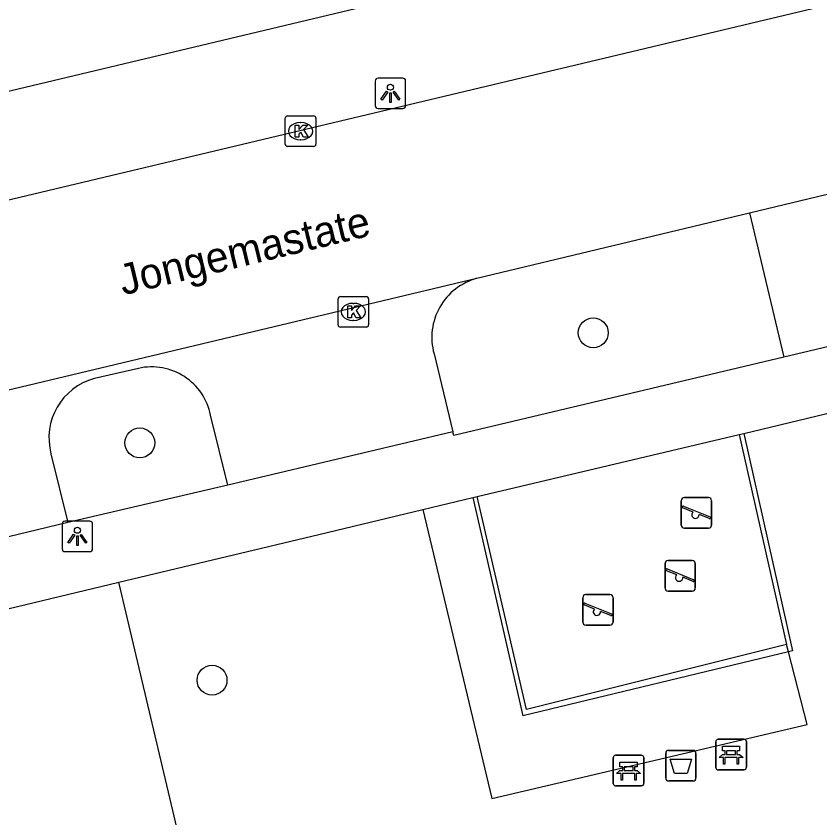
# Model space of a CAD drawing. Extents: x 158038 to 159242, y 380133 to 381214.
# Drawn here: x 158748.37 to 158774.69, y 380454.52 to 380480.77 of the extents above; entities that cross this region are included whole.
import ezdxf

# ---------------------------------------------------------------- set-up
doc = ezdxf.new("R2010")
doc.units = 0
for name, color, linetype in [('IMGEO_Afvalbak', 7, 'Continuous'), ('IMGEO_Bank', 7, 'Continuous'), ('IMGEO_Boom', 7, 'Continuous'), ('IMGEO_Groenvoorziening', 7, 'Continuous'), ('IMGEO_Hek', 7, 'Continuous'), ('IMGEO_Kolk', 7, 'Continuous'), ('IMGEO_Lichtpunt', 7, 'Continuous'), ('IMGEO_Openbare_ruimte_label', 7, 'Continuous'), ('IMGEO_Parkeervlak_open', 7, 'Continuous'), ('IMGEO_Rijbaan_lokaal_open', 7, 'Continuous'), ('IMGEO_Speelvoorziening', 7, 'Continuous'), ('IMGEO_Voetpad_open', 7, 'Continuous')]:
    doc.layers.add(name, color=color, linetype=linetype)

msp = doc.modelspace()

# ---------------------------------------------------------------- linework, layer by layer
at = {"layer": 'IMGEO_Afvalbak'}
for p, q in [((158769.638, 380455.829), (158769.638, 380456.629)), ((158769.638, 380456.629), (158769.638, 380455.829)), ((158769.738, 380456.729), (158770.528, 380456.729)), ((158770.528, 380456.729), (158769.738, 380456.729)), ((158770.628, 380456.629), (158770.628, 380455.829)), ((158770.628, 380455.829), (158770.628, 380456.629)), ((158770.528, 380455.729), (158769.738, 380455.729)), ((158769.738, 380455.729), (158770.528, 380455.729))]:
    msp.add_line(p, q, dxfattribs=at)
msp.add_lwpolyline([(158769.781, 380456.443), (158770.485, 380456.443), (158770.336, 380455.973), (158769.93, 380455.973), (158769.781, 380456.443)], dxfattribs=at)
for centre, start, end in [((158769.738, 380456.629), 90, 180), ((158769.738, 380456.629), 90, 180), ((158770.528, 380456.629), 0, 90), ((158770.528, 380456.629), 360, 90), ((158769.738, 380455.829), 180, 270), ((158769.738, 380455.829), 180, 270), ((158770.528, 380455.829), 270, 0), ((158770.528, 380455.829), 270, 0)]:
    msp.add_arc(centre, 0.1, start, end, dxfattribs=at)
at = {"layer": 'IMGEO_Bank'}
for p, q in [((158771.353, 380457.094), (158772.194, 380457.094)), ((158772.194, 380457.094), (158771.353, 380457.094)), ((158771.278, 380456.169), (158771.278, 380457.01)), ((158771.278, 380457.01), (158771.278, 380456.169)), ((158772.278, 380457.019), (158772.278, 380456.178)), ((158772.278, 380456.178), (158772.278, 380457.019)), ((158767.996, 380456.57), (158768.837, 380456.57)), ((158768.837, 380456.57), (158767.996, 380456.57)), ((158771.587, 380456.6), (158771.587, 380456.706)), ((158771.631, 380456.706), (158771.631, 380456.6)), ((158771.919, 380456.712), (158771.637, 380456.712)), ((158771.637, 380456.594), (158771.919, 380456.594)), ((158771.925, 380456.6), (158771.925, 380456.706)), ((158771.969, 380456.706), (158771.969, 380456.6)), ((158767.921, 380455.645), (158767.921, 380456.486)), ((158767.921, 380456.486), (158767.921, 380455.645)), ((158768.921, 380456.495), (158768.921, 380455.654)), ((158768.921, 380455.654), (158768.921, 380456.495)), ((158771.975, 380456.492), (158771.582, 380456.492)), ((158768.23, 380456.076), (158768.23, 380456.182)), ((158768.274, 380456.182), (158768.274, 380456.076)), ((158768.562, 380456.188), (158768.28, 380456.188)), ((158768.28, 380456.07), (158768.562, 380456.07)), ((158768.568, 380456.076), (158768.568, 380456.182)), ((158768.612, 380456.182), (158768.612, 380456.076)), ((158772.203, 380456.094), (158771.362, 380456.094)), ((158771.362, 380456.094), (158772.203, 380456.094)), ((158768.618, 380455.968), (158768.225, 380455.968)), ((158768.846, 380455.57), (158768.005, 380455.57)), ((158768.005, 380455.57), (158768.846, 380455.57))]:
    msp.add_line(p, q, dxfattribs=at)
for points in [[(158771.581, 380456.712), (158771.495, 380456.712), (158771.495, 380456.873), (158772.058, 380456.873), (158772.058, 380456.712), (158771.975, 380456.712)], [(158771.525, 380456.492), (158771.383, 380456.492), (158771.495, 380456.594), (158771.581, 380456.594)], [(158771.975, 380456.594), (158772.058, 380456.594), (158772.17, 380456.492), (158772.031, 380456.492)], [(158768.224, 380456.188), (158768.138, 380456.188), (158768.138, 380456.349), (158768.701, 380456.349), (158768.701, 380456.188), (158768.618, 380456.188)], [(158771.575, 380456.485), (158771.575, 380456.278), (158771.532, 380456.278), (158771.532, 380456.485)], [(158772.025, 380456.485), (158772.025, 380456.278), (158771.981, 380456.278), (158771.981, 380456.485)], [(158768.168, 380455.968), (158768.026, 380455.968), (158768.138, 380456.07), (158768.224, 380456.07)], [(158768.618, 380456.07), (158768.701, 380456.07), (158768.813, 380455.968), (158768.674, 380455.968)], [(158768.218, 380455.961), (158768.218, 380455.754), (158768.175, 380455.754), (158768.175, 380455.961)], [(158768.668, 380455.961), (158768.668, 380455.754), (158768.624, 380455.754), (158768.624, 380455.961)]]:
    msp.add_lwpolyline(points, dxfattribs=at)
for centre, radius, start, end in [((158771.356, 380457.016), 0.0779, 92.4484, 184.2845), ((158771.356, 380457.016), 0.0779, 92.4484, 184.2845), ((158772.2, 380457.016), 0.0779, 2.4484, 94.2845), ((158772.2, 380457.016), 0.0779, 2.4484, 94.2845), ((158767.999, 380456.492), 0.0779, 92.4484, 184.2845), ((158767.999, 380456.492), 0.0779, 92.4484, 184.2845), ((158768.843, 380456.492), 0.0779, 2.4484, 94.2845), ((158768.843, 380456.492), 0.0779, 2.4484, 94.2845), ((158771.58, 380456.705), 0.00671, 2.8957, 87.1043), ((158771.58, 380456.601), 0.00671, 272.8957, 357.1043), ((158771.637, 380456.705), 0.00671, 92.8957, 177.1043), ((158771.637, 380456.601), 0.00671, 182.8957, 267.1043), ((158771.919, 380456.705), 0.00671, 2.8957, 87.1043), ((158771.919, 380456.601), 0.00671, 272.8957, 357.1043), ((158771.976, 380456.705), 0.00671, 92.8957, 177.1043), ((158771.976, 380456.601), 0.00671, 182.8957, 267.1043), ((158771.525, 380456.485), 0.00671, 2.8957, 87.1043), ((158771.582, 380456.485), 0.00671, 92.8957, 177.1043), ((158771.974, 380456.485), 0.00671, 2.8957, 87.1043), ((158772.031, 380456.485), 0.00671, 92.8957, 177.1043), ((158768.223, 380456.181), 0.00671, 2.8957, 87.1043), ((158768.223, 380456.077), 0.00671, 272.8957, 357.1043), ((158768.28, 380456.181), 0.00671, 92.8957, 177.1043), ((158768.28, 380456.077), 0.00671, 182.8957, 267.1043), ((158768.562, 380456.181), 0.00671, 2.8957, 87.1043), ((158768.562, 380456.077), 0.00671, 272.8957, 357.1043), ((158768.619, 380456.181), 0.00671, 92.8957, 177.1043), ((158768.619, 380456.077), 0.00671, 182.8957, 267.1043), ((158771.356, 380456.172), 0.0779, 182.4484, 274.2845), ((158771.356, 380456.172), 0.0779, 182.4484, 274.2845), ((158772.2, 380456.172), 0.0779, 272.4484, 4.2845), ((158772.2, 380456.172), 0.0779, 272.4484, 4.2845), ((158768.168, 380455.961), 0.00671, 2.8957, 87.1043), ((158768.225, 380455.961), 0.00671, 92.8957, 177.1043), ((158768.617, 380455.961), 0.00671, 2.8957, 87.1043), ((158768.674, 380455.961), 0.00671, 92.8957, 177.1043), ((158767.999, 380455.648), 0.0779, 182.4484, 274.2845), ((158767.999, 380455.648), 0.0779, 182.4484, 274.2845), ((158768.843, 380455.648), 0.0779, 272.4484, 4.2845), ((158768.843, 380455.648), 0.0779, 272.4484, 4.2845)]:
    msp.add_arc(centre, radius, start, end, dxfattribs=at)
at = {"layer": 'IMGEO_Boom'}
for centre in [(158767.265, 380470.403), (158752.42, 380466.797), (158754.786, 380459.028)]:
    msp.add_circle(centre, 0.489, dxfattribs=at)
at = {"layer": 'IMGEO_Groenvoorziening'}
for points in [[(158772.376, 380474.328), (158773.5, 380469.6)], [(158772.046, 380467.073), (158773.593, 380460.202)], [(158674.708, 380422.973), (158675.136, 380421.076), (158676.506, 380415.389), (158677.716, 380410.364), (158686.692, 380412.003), (158702.709, 380415.812), (158716.247, 380419.298), (158716.347, 380418.923), (158726.817, 380421.283), (158741.196, 380424.551), (158759.516, 380429.33), (158758.315, 380434.41), (158751.736, 380462.236)]]:
    msp.add_lwpolyline(points, dxfattribs=at)
at = {"layer": 'IMGEO_Hek'}
for points in [[(158772.046, 380467.073), (158772.195, 380467.109)], [(158772.195, 380467.109), (158773.788, 380459.994)], [(158763.465, 380465.045), (158772.046, 380467.073)], [(158763.327, 380465.012), (158763.465, 380465.045)], [(158763.327, 380465.012), (158764.965, 380457.863)], [(158773.788, 380459.994), (158773.655, 380459.962)], [(158773.655, 380459.962), (158764.965, 380457.863)]]:
    msp.add_lwpolyline(points, dxfattribs=at)
at = {"layer": 'IMGEO_Kolk'}
for p, q in [((158757.184, 380476.579), (158757.184, 380477.431)), ((158757.259, 380477.505), (158758.111, 380477.505)), ((158758.185, 380477.431), (158758.185, 380476.579)), ((158757.672, 380477.285), (158757.697, 380477.285)), ((158757.695, 380476.725), (158757.67, 380476.725)), ((158758.111, 380476.505), (158757.259, 380476.505)), ((158758.986, 380471.587), (158759.838, 380471.587)), ((158758.911, 380470.661), (158758.911, 380471.513)), ((158759.399, 380471.367), (158759.424, 380471.367)), ((158759.912, 380471.513), (158759.912, 380470.661)), ((158759.422, 380470.807), (158759.397, 380470.807)), ((158759.838, 380470.587), (158758.986, 380470.587))]:
    msp.add_line(p, q, dxfattribs=at)
for points in [[(158757.184, 380476.579), (158757.184, 380477.431)], [(158757.259, 380477.505), (158758.111, 380477.505)], [(158758.185, 380477.431), (158758.185, 380476.579)], [(158757.505, 380477.205), (158757.628, 380477.205), (158757.628, 380477.054), (158757.758, 380477.205), (158757.922, 380477.205), (158757.776, 380477.054), (158757.929, 380476.805), (158757.777, 380476.805), (158757.692, 380476.969), (158757.628, 380476.902), (158757.628, 380476.805), (158757.505, 380476.805), (158757.505, 380477.205)], [(158758.111, 380476.505), (158757.259, 380476.505)], [(158758.986, 380471.587), (158759.838, 380471.587)], [(158758.911, 380470.661), (158758.911, 380471.513)], [(158759.232, 380471.287), (158759.355, 380471.287), (158759.355, 380471.136), (158759.485, 380471.287), (158759.649, 380471.287), (158759.503, 380471.136), (158759.656, 380470.887), (158759.504, 380470.887), (158759.419, 380471.051), (158759.355, 380470.984), (158759.355, 380470.887), (158759.232, 380470.887), (158759.232, 380471.287)], [(158759.912, 380471.513), (158759.912, 380470.661)], [(158759.838, 380470.587), (158758.986, 380470.587)]]:
    msp.add_lwpolyline(points, dxfattribs=at)
for centre, start, end in [((158757.261, 380477.429), 91.552, 178.448), ((158757.261, 380477.429), 91.552, 178.448), ((158758.109, 380477.429), 1.552, 88.448), ((158758.109, 380477.429), 1.552, 88.448), ((158757.261, 380476.581), 181.552, 268.448), ((158757.261, 380476.581), 181.552, 268.448), ((158758.109, 380476.581), 271.552, 358.448), ((158758.109, 380476.581), 271.552, 358.448), ((158758.988, 380471.511), 91.552, 178.448), ((158758.988, 380471.511), 91.552, 178.448), ((158759.836, 380471.511), 1.552, 88.448), ((158759.836, 380471.511), 1.552, 88.448), ((158758.988, 380470.663), 181.552, 268.448), ((158758.988, 380470.663), 181.552, 268.448), ((158759.836, 380470.663), 271.552, 358.448), ((158759.836, 380470.663), 271.552, 358.448)]:
    msp.add_arc(centre, 0.0765, start, end, dxfattribs=at)
for centre, major_axis, ratio, start_param, end_param in [((158757.671, 380477.005), (-0.387, 0.002), 0.722429, 4.712389, 7.853982), ((158757.696, 380477.005), (-0.39, 0.002), 0.717154, 1.570796, 4.712389), ((158759.398, 380471.087), (-0.387, 0.002), 0.722429, 4.712389, 7.853982), ((158759.423, 380471.087), (-0.39, 0.002), 0.717154, 1.570796, 4.712389)]:
    msp.add_ellipse(centre, major_axis=major_axis, ratio=ratio, start_param=start_param, end_param=end_param, dxfattribs=at)
at = {"layer": 'IMGEO_Lichtpunt'}
for p, q in [((158761.029, 380478.741), (158760.221, 380478.741)), ((158761.029, 380478.741), (158760.221, 380478.741)), ((158760.127, 380478.646), (158760.127, 380477.839)), ((158760.127, 380478.646), (158760.127, 380477.839)), ((158761.123, 380477.839), (158761.123, 380478.646)), ((158761.123, 380477.839), (158761.123, 380478.646)), ((158760.221, 380477.745), (158761.029, 380477.745)), ((158760.221, 380477.745), (158761.029, 380477.745)), ((158750.78, 380464.235), (158749.972, 380464.235)), ((158750.78, 380464.235), (158749.972, 380464.235)), ((158749.878, 380464.14), (158749.878, 380463.333)), ((158749.878, 380464.14), (158749.878, 380463.333)), ((158750.874, 380463.333), (158750.874, 380464.14)), ((158750.874, 380463.333), (158750.874, 380464.14)), ((158749.972, 380463.239), (158750.78, 380463.239)), ((158749.972, 380463.239), (158750.78, 380463.239))]:
    msp.add_line(p, q, dxfattribs=at)
for points in [[(158760.501, 380478.31), (158760.54, 380478.282), (158760.352, 380478.02), (158760.314, 380478.047), (158760.501, 380478.31)], [(158760.603, 380478.262), (158760.65, 380478.262), (158760.65, 380477.94), (158760.603, 380477.94), (158760.603, 380478.262)], [(158760.713, 380478.282), (158760.751, 380478.309), (158760.938, 380478.047), (158760.899, 380478.019), (158760.713, 380478.282)], [(158750.252, 380463.804), (158750.291, 380463.776), (158750.103, 380463.514), (158750.065, 380463.541), (158750.252, 380463.804)], [(158750.354, 380463.756), (158750.401, 380463.756), (158750.401, 380463.434), (158750.354, 380463.434), (158750.354, 380463.756)], [(158750.464, 380463.776), (158750.502, 380463.803), (158750.689, 380463.541), (158750.65, 380463.513), (158750.464, 380463.776)]]:
    msp.add_lwpolyline(points, dxfattribs=at)
for centre in [(158760.626, 380478.444), (158750.377, 380463.938)]:
    msp.add_circle(centre, 0.0994, dxfattribs=at)
for centre, start, end in [((158760.221, 380478.646), 90, 180), ((158760.221, 380478.646), 90, 180), ((158761.029, 380478.646), 0, 90), ((158761.029, 380478.646), 0, 90), ((158760.221, 380477.839), 180, 270), ((158760.221, 380477.839), 180, 270), ((158761.029, 380477.839), 270, 0), ((158761.029, 380477.839), 270, 360), ((158749.972, 380464.14), 90, 180), ((158749.972, 380464.14), 90, 180), ((158750.78, 380464.14), 0, 90), ((158750.78, 380464.14), 0, 90), ((158749.972, 380463.333), 180, 270), ((158749.972, 380463.333), 180, 270), ((158750.78, 380463.333), 270, 0), ((158750.78, 380463.333), 270, 360)]:
    msp.add_arc(centre, 0.0946, start, end, dxfattribs=at)
at = {"layer": 'IMGEO_Parkeervlak_open'}
for points in [[(158762.053, 380469.717), (158762.671, 380467.165)], [(158752.38, 380469.238), (158750.933, 380468.905)], [(158755.302, 380465.417), (158754.736, 380467.703)], [(158749.512, 380466.439), (158750.063, 380464.186)]]:
    msp.add_lwpolyline(points, dxfattribs=at)
for centre, radius, start, end in [((158763.984, 380470.252), 2.004, 105.1968, 195.4836), ((158752.81, 380467.322), 1.964, 11.1865, 102.6428), ((158751.466, 380466.956), 2.021, 105.2847, 194.811)]:
    msp.add_arc(centre, radius, start, end, dxfattribs=at)
at = {"layer": 'IMGEO_Rijbaan_lokaal_open'}
for points in [[(158783.564, 380483.19), (158721.16, 380468.328)], [(158772.376, 380474.328), (158777.928, 380475.662)], [(158763.459, 380472.186), (158772.376, 380474.328)], [(158723.45, 380462.655), (158763.459, 380472.186)]]:
    msp.add_lwpolyline(points, dxfattribs=at)
at = {"layer": 'IMGEO_Speelvoorziening'}
for p, q in [((158770.249, 380465.005), (158771.039, 380465.005)), ((158771.039, 380465.005), (158770.249, 380465.005)), ((158770.149, 380464.105), (158770.149, 380464.905)), ((158770.149, 380464.905), (158770.149, 380464.105)), ((158770.218, 380464.73), (158771.094, 380464.377)), ((158771.139, 380464.905), (158771.139, 380464.105)), ((158771.139, 380464.105), (158771.139, 380464.905)), ((158770.532, 380464.533), (158770.193, 380464.67)), ((158771.07, 380464.317), (158770.73, 380464.454)), ((158771.039, 380464.005), (158770.249, 380464.005)), ((158770.249, 380464.005), (158771.039, 380464.005)), ((158769.715, 380462.947), (158770.505, 380462.947)), ((158770.505, 380462.947), (158769.715, 380462.947)), ((158769.615, 380462.047), (158769.615, 380462.847)), ((158769.615, 380462.847), (158769.615, 380462.047)), ((158769.998, 380462.475), (158769.659, 380462.612)), ((158769.684, 380462.672), (158770.56, 380462.319)), ((158770.605, 380462.847), (158770.605, 380462.047)), ((158770.605, 380462.047), (158770.605, 380462.847)), ((158770.536, 380462.259), (158770.196, 380462.396)), ((158767.022, 380461.829), (158767.812, 380461.829)), ((158767.812, 380461.829), (158767.022, 380461.829)), ((158770.505, 380461.947), (158769.715, 380461.947)), ((158769.715, 380461.947), (158770.505, 380461.947)), ((158766.922, 380460.929), (158766.922, 380461.729)), ((158766.922, 380461.729), (158766.922, 380460.929)), ((158766.991, 380461.554), (158767.867, 380461.201)), ((158767.912, 380461.729), (158767.912, 380460.929)), ((158767.912, 380460.929), (158767.912, 380461.729)), ((158767.305, 380461.357), (158766.966, 380461.494)), ((158767.843, 380461.141), (158767.503, 380461.278)), ((158767.812, 380460.829), (158767.022, 380460.829)), ((158767.022, 380460.829), (158767.812, 380460.829))]:
    msp.add_line(p, q, dxfattribs=at)
for centre, radius, start, end in [((158770.249, 380464.905), 0.1, 90, 180), ((158770.249, 380464.905), 0.1, 90, 180), ((158771.039, 380464.905), 0.1, 0, 90), ((158771.039, 380464.905), 0.1, 360, 90), ((158770.206, 380464.7), 0.0327, 68.078, 248.078), ((158770.611, 380464.443), 0.12, 130.9928, 5.1632), ((158771.082, 380464.347), 0.0327, 248.078, 68.078), ((158770.249, 380464.105), 0.1, 180, 270), ((158770.249, 380464.105), 0.1, 180, 270), ((158771.039, 380464.105), 0.1, 270, 0), ((158771.039, 380464.105), 0.1, 270, 0), ((158769.715, 380462.847), 0.1, 90, 180), ((158769.715, 380462.847), 0.1, 90, 180), ((158770.505, 380462.847), 0.1, 0, 90), ((158770.505, 380462.847), 0.1, 360, 90), ((158769.672, 380462.642), 0.0327, 68.078, 248.078), ((158770.077, 380462.385), 0.12, 130.9928, 5.1632), ((158770.548, 380462.289), 0.0327, 248.078, 68.078), ((158767.022, 380461.729), 0.1, 90, 180), ((158767.022, 380461.729), 0.1, 90, 180), ((158767.812, 380461.729), 0.1, 0, 90), ((158767.812, 380461.729), 0.1, 360, 90), ((158769.715, 380462.047), 0.1, 180, 270), ((158769.715, 380462.047), 0.1, 180, 270), ((158770.505, 380462.047), 0.1, 270, 0), ((158770.505, 380462.047), 0.1, 270, 0), ((158766.979, 380461.524), 0.0327, 68.078, 248.078), ((158767.384, 380461.267), 0.12, 130.9928, 5.1632), ((158767.855, 380461.171), 0.0327, 248.078, 68.078), ((158767.022, 380460.929), 0.1, 180, 270), ((158767.022, 380460.929), 0.1, 180, 270), ((158767.812, 380460.929), 0.1, 270, 0), ((158767.812, 380460.929), 0.1, 270, 0)]:
    msp.add_arc(centre, radius, start, end, dxfattribs=at)
at = {"layer": 'IMGEO_Voetpad_open'}
for points in [[(158782.764, 380486.561), (158720.337, 380471.694), (158717.742, 380471.085)], [(158787.413, 380472.903), (158773.5, 380469.6)], [(158773.5, 380469.6), (158762.702, 380467.037), (158762.671, 380467.165)], [(158772.046, 380467.073), (158772.195, 380467.109), (158782.3, 380469.539)], [(158762.671, 380467.165), (158755.302, 380465.417)], [(158763.465, 380465.045), (158772.046, 380467.073)], [(158755.302, 380465.417), (158750.063, 380464.186)], [(158761.689, 380464.62), (158763.327, 380465.012), (158763.465, 380465.045)], [(158773.593, 380460.202), (158765.081, 380458.064), (158763.465, 380465.045)], [(158751.736, 380462.236), (158755.259, 380463.08), (158758.277, 380463.803), (158761.689, 380464.62)], [(158761.689, 380464.62), (158763.95, 380455.159), (158774.268, 380457.575), (158773.655, 380459.962), (158773.593, 380460.202)], [(158750.063, 380464.186), (158745.135, 380463.007)], [(158746.999, 380461.102), (158751.736, 380462.236)]]:
    msp.add_lwpolyline(points, dxfattribs=at)

# ---------------------------------------------------------------- texts
at = {"layer": 'IMGEO_Openbare_ruimte_label'}
msp.add_text('Jongemastate', height=1, rotation=13.5916, dxfattribs=at).set_placement((158751.873, 380471.625))

doc.saveas('drawing.dxf')
